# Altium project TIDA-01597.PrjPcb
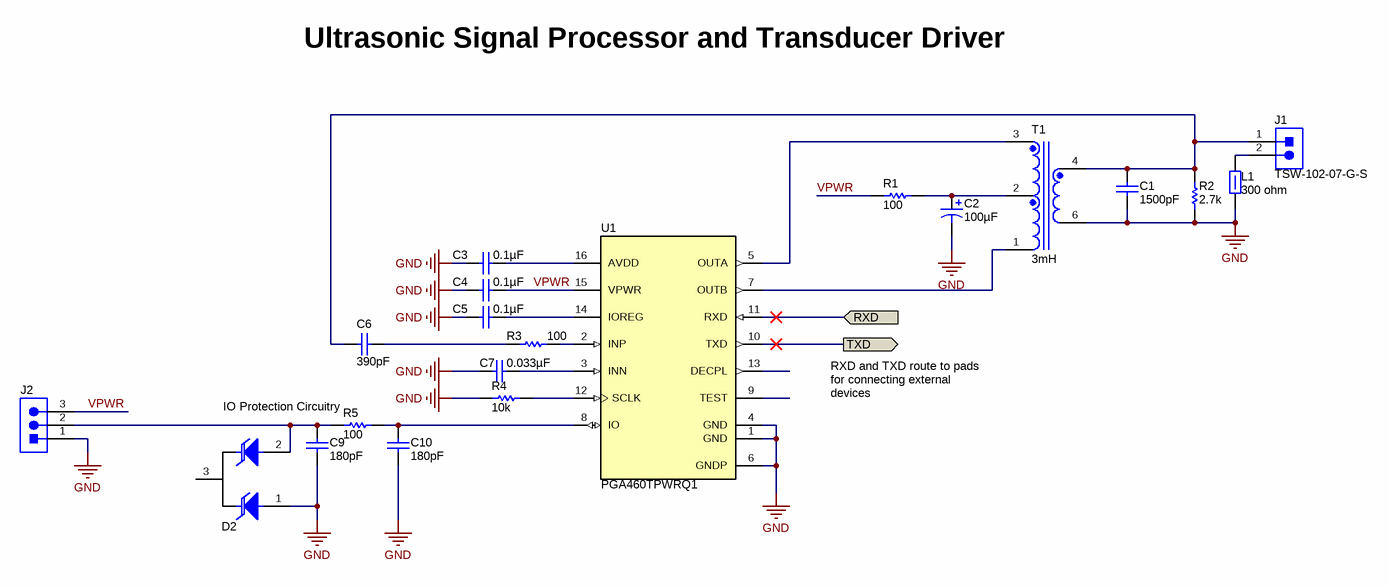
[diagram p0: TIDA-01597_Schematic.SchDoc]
CopyrightYear: 2017; EVM_Orderable: N/A; PCB_Layout: Luis Cordova; PCB_Rev: E1; PRJ_Customer: N/A; PRJ_Engineer: Luis Cordova; PRJ_Number: TIDA-01597; PRJ_Title: Ultrasonic Object Detection for Park Assist; SCH_Rev: E1; TechSupport: http://www.ti.com/support; TID: TIDA-01597
4 sheets, 43 parts. Net scope: flat (ports and power ports of the same name join across sheets).
Board file: TIDA-01597_PCB.PcbDoc
Sheets:
  TIDA-01597_Schematic.SchDoc
  TIDA-01597_CoverSheet.SchDoc
  TIDA-01597_EVMHardware.SchDoc
  TCI-level-translator.SchDoc

## Sheet TIDA-01597_Schematic.SchDoc
size 431 x 279 mm; Date: Not shown in title block; ApprovedBy: Not shown in title block; CheckedBy: Not shown in title block; Author: Not shown in title block; CompanyName: Not shown in title block; Engineer: Not shown in title block; Organization: Not shown in title block; Address1: Not shown in title block; Address2: Not shown in title block; Address3: Not shown in title block; Address4: Not shown in title block; DocumentNumber: 1; Revision: Use project parameter SCH_Rev; SheetNumber: 2; SheetTotal: 3; PageSetup: Record=PageOptions¦CenterHorizontal=True¦CenterVertical=True¦PrintScale=0.64¦XCorrection=1.00¦YCorrection=1.00¦PrintKind=0¦BorderSize=5000000¦LeftOffset=0¦BottomOffset=0¦Orientation=2¦PaperLength=1000¦PaperWidth=1000¦Scale=100¦PaperSource=15¦PrintQuality=600¦MediaType=1¦DitherType=10¦PrintScaleMode=1¦PaperKind=Letter

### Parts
C1  ValueDisplayed: 1500pF  [0603]  (hidden comment: GRM188R72A152KA01D)
C2  ValueDisplayed: 100µF  [SM_RADIAL_F]  (hidden comment: EEE-FK1V101P)
C3  ValueDisplayed: 0.1µF  [0603M]  (hidden comment: C1608X7R1E104K080AA)
C4  ValueDisplayed: 0.1µF  [0603L]  (hidden comment: C1608X7R1E104K080AA)
C5  ValueDisplayed: 0.1µF  [0603L]  (hidden comment: C1608X7R1E104K080AA)
C6  ValueDisplayed: 390pF  [0603]  (hidden comment: GRM1885C2A391JA01D)
C7  ValueDisplayed: 0.033µF  [0603]  (hidden comment: 06035C333JAT2A)
C9  ValueDisplayed: 180pF  [0603]  (hidden comment: GRM1885C1H181JA01D)
C10  ValueDisplayed: 180pF  [0603]  (hidden comment: GRM1885C1H181JA01D)
D2  MMBZ27VCL-7-F  [SOT-23]  (value not drawn)
J1  TSW-102-07-G-S  [TSW-102-07-G-S]
J2  TSW-103-07-G-S  [TSW-103-07-G-S]  (value not drawn)
L1  ValueDisplayed: 300 ohm  [0603]  (hidden comment: 74279264)
R1  ValueDisplayed: 100  [0603]  (hidden comment: CRCW0603100RJNEA)
R2  ValueDisplayed: 2.7k  [0603]  (hidden comment: RC0603JR-072K7L)
R3  ValueDisplayed: 100  [0603]  (hidden comment: CRCW0603100RJNEA)
R4  ValueDisplayed: 10k  [0603L]  (hidden comment: RC0603JR-0710KL)
R5  ValueDisplayed: 100  [0603]  (hidden comment: CRCW0603100RFKEA)
T1  ValueDisplayed: 3mH  [TDK_B78416A2232A003]  (hidden comment: B78416A2232A003)
U1  PGA460TPWRQ1  [PW0016A_N]

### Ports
RXD (in), TXD (out)

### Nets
GND: C1.2 C2.2(-) C3.2 C4.2 C5.2 C7.2 C9.2 C10.2 D2.1 J2.1 L1.1 R2.1 R4.1 T1.6 U1.1(GND) U1.4(GND) U1.6(GNDP)
RXD: U1.11(RXD) ; port RXD
TXD: U1.10(TXD) ; port TXD
VPWR: C4.1 J2.3 R1.2 U1.15(VPWR)
NetC1_1: C1.1 C6.2 J1.1 R2.2 T1.4
NetC2_1: C2.1(+) R1.1 T1.2
NetC3_1: C3.1 U1.16(AVDD)
NetC5_1: C5.1 U1.14(IOREG)
NetC6_1: C6.1 R3.1
NetC7_1: C7.1 U1.3(INN)
NetC9_1: C9.1 D2.2 J2.2 R5.1
NetC10_1: C10.1 R5.2 U1.8(IO)
NetJ1_2: J1.2 L1.2
NetR3_2: R3.2 U1.2(INP)
NetR4_2: R4.2 U1.12(SCLK)
NetT1_1: T1.1 U1.7(OUTB)
NetT1_3: T1.3 U1.5(OUTA)

Not connected (* = marked no-connect by the designer): D2 3; U1 9(TEST) 13(DECPL)

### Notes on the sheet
- Ultrasonic Signal Processor and Transducer Driver
- (near R5) IO Protection Circuitry
- RXD and TXD route to pads for connecting external devices

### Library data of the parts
C1 = GRM188R72A152KA01D: CAP, CERM, 1500 pF, 100 V, +/- 10%, X7R, 0603; Manufacturer: MuRata; Polarized: N; CompType: Capacitor; Value: 1500pF; U/M: EA; Cap_F: 0.0000000015; Tolerance_%: 10; Value1: Unknown; VDC_V: 100; Value2: 100V; TaMin_C: -55; TaMax_C: 125; SizeArea_mm2: 1.28; SizeAreaWB_mm2: 4.68; SizeX_mm: 1.6; SizeY_mm: 0.8; SizeZ_mm: 1; AEC Category: Q200
C2 = EEE-FK1V101P: CAP, AL, 100 µF, 35 V, +/- 20%, 0.16 ohm, AEC-Q200 Grade 2, SMD; Manufacturer: Panasonic; Polarized: Y; CompType: Capacitor; Value: 100uF; U/M: EA; Cap_F: 0.0001; Tolerance_%: 20; VDC_V: 35; Value2: 35V; ESR_ohm: 0.16; IRMS_A: 0.6; TaMin_C: -55; TaMax_C: 105; Cap_Case: F; SizeAreaWB_mm2: 123.6; SizeArea_mm2: 83; SizeX_mm: 10; SizeY_mm: 8.3; SizeZ_mm: 10.2; AEC Category: Q200; AEC Grade: 2
C3-C5 = C1608X7R1E104K080AA: CAP, CERM, 0.1 µF, 25 V, +/- 10%, X7R, 0603; Manufacturer: TDK; Polarized: N; CompType: Capacitor; Value: 0.1uF; U/M: EA; Cap_F: 0.0000001; Tolerance_%: 10; Value1: Unknown; VDC_V: 25; Value2: 25V; TaMin_C: -55; TaMax_C: 125; Cap_Case: 0603; SizeArea_mm2: 1.28; SizeAreaWB_mm2: 4.68; SizeX_mm: 1.6; SizeY_mm: 0.8; SizeZ_mm: 1; AEC Category: Q200
C6 = GRM1885C2A391JA01D: CAP, CERM, 390 pF, 100 V, +/- 5%, C0G/NP0, 0603; Manufacturer: MuRata; Polarized: N; CompType: Capacitor; Value: 390pF; U/M: EA; Cap_F: 0.00000000039; Tolerance_%: 5; Value1: Unknown; VDC_V: 100; Value2: 100V; TaMin_C: -55; TaMax_C: 125; SizeArea_mm2: 1.28; SizeAreaWB_mm2: 4.68; SizeX_mm: 1.6; SizeY_mm: 0.8; SizeZ_mm: 1; AEC Category: Q200
C7 = 06035C333JAT2A: CAP, CERM, 0.033 µF, 50 V, +/- 5%, X7R, 0603; Manufacturer: AVX; Polarized: N; CompType: Capacitor; Value: 0.033uF; U/M: EA; Cap_F: 0.000000033; Tolerance_%: 5; Value1: Unknown; VDC_V: 50; Value2: 50V; TaMin_C: -55; TaMax_C: 125; SizeArea_mm2: 1.28; SizeAreaWB_mm2: 4.68; SizeX_mm: 1.6; SizeY_mm: 0.8; SizeZ_mm: 1; AEC Category: Q200
C9 C10 = GRM1885C1H181JA01D: CAP, CERM, 180 pF, 50 V,+/- 5%, C0G/NP0, 0603; Manufacturer: MuRata; Polarized: N; CompType: Capacitor; Value: 180pF; U/M: EA; Cap_F: 0.00000000018; Tolerance_%: 5; VDC_V: 50; Value2: 50V; TaMin_C: -55; TaMax_C: 125; SizeArea_mm2: 1.28; SizeAreaWB_mm2: 4.68; SizeX_mm: 1.6; SizeY_mm: 0.8; SizeZ_mm: 1; AEC Category: Q200; Green_Lifecycle: Active; Green_REACh: Passed
D2 = MMBZ27VCL-7-F: Diode, TVS, Uni, 27 V, 38 Vc, SOT-23; Manufacturer: Diodes Inc.; SymbolCreator: a0411947; Value: 27V; U/M: EA; Power_W: 0.225; Vr_V: 27; Value1: 0.225W; RJA_CperW: 556; SizeAreaWB_mm2: 14; SizeArea_mm2: 7.5; SizeX_mm: 2.5; SizeY_mm: 3; SizeZ_mm: 1.1; AEC Category: Q101; AEC Qualified: N
J1 = TSW-102-07-G-S: Header, 100mil, 2x1, Gold, TH; Manufacturer: Samtec; SymbolCreator: a0412235; Pitch_mm: 2.54; Gender: Male; Shrouded: N; Row_Count: 1; Current_A: 6.3; Voltage_V: 550; Cert_CSA: Y
J2 = TSW-103-07-G-S: Header, 100mil, 3x1, Gold, TH; Manufacturer: Samtec; SymbolCreator: a0799628; Pitch_mm: 2.54; Gender: Male; Shrouded: N; Row_Count: 1; Current_A: 6.3; Voltage_V: 550; Cert_CSA: Y
L1 = 74279264: Ferrite Bead, 300 ohm @ 100 MHz, 0.2 A, 0603; Manufacturer: Wurth Elektronik; Value: 300 ohm; Imax_A: 0.2; DCR_ohm: 0.35; Value1: 0.35 ohm; Value2: 0.2A; SizeAreaWB_mm2: 4.68; SizeArea_mm2: 1.28; SizeX_mm: 1.6; SizeY_mm: 0.8; SizeZ_mm: 1; ZTyp@100MHz_Ohm: 300; Ztyp@1GHz_Ohm: 279.491
R1 = CRCW0603100RJNEA: RES, 100, 5%, 0.1 W, 0603; Manufacturer: Vishay-Dale; CompType: Resistor; Value: 100; Value_Code: 100R; Tolerance_%: 5; Power_W: 0.1; Value2: 0.1W; VDC_V: 75; TempCo: 200 ppm/C; SizeArea_mm2: 1.28; SizeX_mm: 1.6; SizeY_mm: 0.8; SizeZ_mm: 1; EIA_Code: E24; U/M: EA; AEC Category: Q200; Green_Lifecycle: Active; Green_REACh: Passed
R2 = RC0603JR-072K7L: RES, 2.7 k, 5%, 0.1 W, 0603; Manufacturer: Yageo America; CompType: Resistor; Value: 2.7k; Res_ohm: 2700; Value_Code: 2k70; Tolerance_%: 5; Power_W: 0.1; Value2: 0.1W; VDC_V: 50; TempCo: 100 ppm/C; SizeArea_mm2: 1.28; SizeX_mm: 1.6; SizeY_mm: 0.8; SizeZ_mm: 1; EIA_Code: E24; U/M: EA; AEC Category: Q200
R3 = CRCW0603100RJNEA: RES, 100, 5%, 0.1 W, 0603; Manufacturer: Vishay-Dale; CompType: Resistor; Value: 100; Value_Code: 100R; Tolerance_%: 5; Power_W: 0.1; Value2: 0.1W; VDC_V: 75; TempCo: 200 ppm/C; SizeArea_mm2: 1.28; SizeX_mm: 1.6; SizeY_mm: 0.8; SizeZ_mm: 1; EIA_Code: E24; U/M: EA; AEC Category: Q200
R4 = RC0603JR-0710KL: RES, 10 k, 5%, 0.1 W, 0603; Manufacturer: Yageo America; CompType: Resistor; Value: 10k; Res_ohm: 10000; Value_Code: 10k0; Tolerance_%: 5; Power_W: 0.1; Value2: 0.1W; VDC_V: 50; TempCo: 100 ppm/C; SizeArea_mm2: 1.28; SizeX_mm: 1.6; SizeY_mm: 0.8; SizeZ_mm: 1; EIA_Code: E24; U/M: EA; AEC Category: Q200
R5 = CRCW0603100RFKEA: RES, 100, 1%, 0.1 W, 0603; Manufacturer: Vishay-Dale; CompType: Resistor; Value: 100; Value_Code: 100R; Tolerance_%: 1; Power_W: 0.1; Value2: 0.1W; VDC_V: 75; TempCo: 100 ppm/C; SizeArea_mm2: 1.28; SizeX_mm: 1.6; SizeY_mm: 0.8; EIA_Code: E96; U/M: EA; AEC Category: Q200; Green_Lifecycle: Active; Green_REACh: Passed
T1 = B78416A2232A003: Transformer, 3 mH, SMT; Manufacturer: TDK; SymbolCreator: Altium; Value: 3mH; Lp: 3000; Ns1toNp: 0.1188
U1 = PGA460TPWRQ1: PGA460TPWRQ1, PW0016A (TSSOP-16); Manufacturer: Texas Instruments; SymbolCreator: Altium; SizeArea_mm2: 32; SizeAreaWB_mm2: 58.8; SizeX_mm: 6.4; SizeY_mm: 5; SizeZ_mm: 1.2; CompType: IC; U/M: EA

## Sheet TIDA-01597_CoverSheet.SchDoc
size 431 x 279 mm; Date: Not shown in title block; ApprovedBy: Not shown in title block; CheckedBy: Not shown in title block; Author: Not shown in title block; CompanyName: Not shown in title block; Engineer: Not shown in title block; Organization: Not shown in title block; Address1: Not shown in title block; Address2: Not shown in title block; Address3: Not shown in title block; Address4: Not shown in title block; DocumentNumber: 1; Revision: Use project parameter SCH_Rev; SheetNumber: 1; SheetTotal: 3; PageSetup: Record=PageOptions¦CenterHorizontal=True¦CenterVertical=True¦PrintScale=1.00¦XCorrection=1.00¦YCorrection=1.00¦PrintKind=0¦BorderSize=5000000¦LeftOffset=0¦BottomOffset=0¦Orientation=2¦PaperLength=1000¦PaperWidth=1000¦Scale=100¦PaperSource=15¦PrintQuality=600¦MediaType=1¦DitherType=10¦PaperKind=Letter¦PrintScaleMode=1
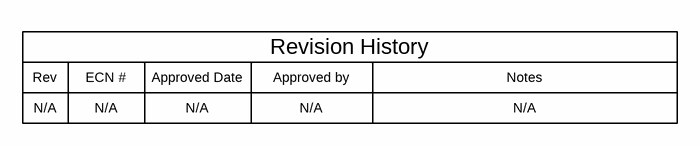
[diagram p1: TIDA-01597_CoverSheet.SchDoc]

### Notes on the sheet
- Rev
- N/A
- ECN #
- Approved Date
- Approved by
- Revision History
- Notes

## Sheet TIDA-01597_EVMHardware.SchDoc
size 431 x 279 mm; Date: Not shown in title block; ApprovedBy: Not shown in title block; CheckedBy: Not shown in title block; Author: Not shown in title block; CompanyName: Not shown in title block; Engineer: Not shown in title block; Organization: Not shown in title block; Address1: Not shown in title block; Address2: Not shown in title block; Address3: Not shown in title block; Address4: Not shown in title block; DocumentNumber: 1; Revision: Use project parameter SCH_Rev; SheetNumber: 3; SheetTotal: 3; PageSetup: Record=PageOptions¦CenterHorizontal=True¦CenterVertical=True¦PrintScale=1.00¦XCorrection=1.00¦YCorrection=1.00¦PrintKind=0¦BorderSize=5000000¦LeftOffset=0¦BottomOffset=0¦Orientation=2¦PaperLength=1000¦PaperWidth=1000¦Scale=100¦PaperSource=15¦PrintQuality=600¦MediaType=1¦DitherType=10¦PaperKind=Letter¦PrintScaleMode=1
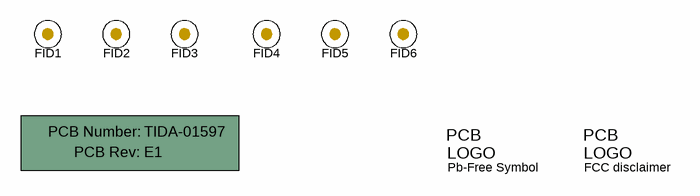
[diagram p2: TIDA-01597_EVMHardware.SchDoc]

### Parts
!PCB1  TIDA-01597  (value not drawn)  (mechanical)
FID1  Fiducial  [Fiducial10-20]  (value not drawn)
FID2  Fiducial  [Fiducial10-20]  (value not drawn)
FID3  Fiducial  [Fiducial10-20]  (value not drawn)
FID4  Fiducial  [Fiducial10-20]  (value not drawn)
FID5  Fiducial  [Fiducial10-20]  (value not drawn)
FID6  Fiducial  [Fiducial10-20]  (value not drawn)
Logo2  Pb-Free Symbol  [Pb-Free_Overlay_Small]  (no BOM)
Logo3  FCC disclaimer  [FCC_disclaimer]  (no BOM)

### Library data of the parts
!PCB1 = PCB: Printed Circuit Board; Manufacturer: Any; SymbolCreator: a0412235
FID1-FID6 = Fiducial: Fiducial mark.  There is nothing to buy or mount.; SymbolCreator: codlsc
Logo2 = Pb-Free: SymbolCreator: a0412235
Logo3 = FCC_disclaimer: SymbolCreator: codlsc

## Sheet TCI-level-translator.SchDoc
size 431 x 279 mm; Date: Not shown in title block; ApprovedBy: Not shown in title block; CheckedBy: Not shown in title block; Author: Not shown in title block; CompanyName: Not shown in title block; Engineer: Not shown in title block; Organization: Not shown in title block; Address1: Not shown in title block; Address2: Not shown in title block; Address3: Not shown in title block; Address4: Not shown in title block; DocumentNumber: 1; Revision: Use project parameter SCH_Rev; SheetNumber: 2; SheetTotal: 3; PageSetup: Record=PageOptions¦CenterHorizontal=True¦CenterVertical=True¦PrintScale=1.00¦XCorrection=1.00¦YCorrection=1.00¦PrintKind=0¦BorderSize=5000000¦LeftOffset=0¦BottomOffset=0¦Orientation=2¦PaperLength=1000¦PaperWidth=1000¦Scale=100¦PaperSource=15¦PrintQuality=600¦MediaType=1¦DitherType=10¦PaperKind=Letter¦PrintScaleMode=1
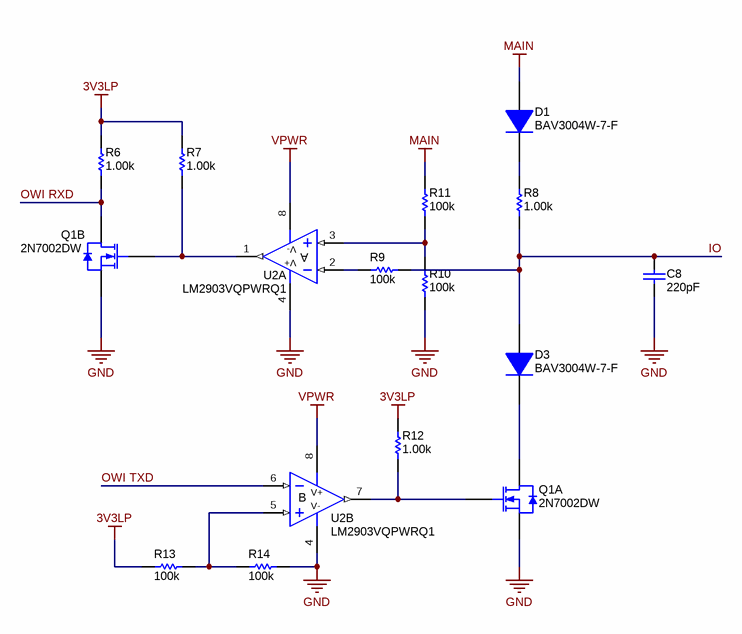
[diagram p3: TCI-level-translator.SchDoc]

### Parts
C8  ValueDisplayed: 220pF  [0603]  (hidden comment: 06031C221KAT2A)
D1  BAV3004W-7-F  [SOD-123]
D3  BAV3004W-7-F  [SOD-123]
Q1  2N7002DW  [SOT-363]  (parts A,B of 2)
R6  ValueDisplayed: 1.00k  [0603]  (hidden comment: CRCW06031K00FKEA)
R7  ValueDisplayed: 1.00k  [0603]  (hidden comment: CRCW06031K00FKEA)
R8  ValueDisplayed: 1.00k  [0603]  (hidden comment: CRCW06031K00FKEA)
R9  ValueDisplayed: 100k  [0603]  (hidden comment: CRCW0603100KFKEA)
R10  ValueDisplayed: 100k  [0603]  (hidden comment: CRCW0603100KFKEA)
R11  ValueDisplayed: 100k  [0603]  (hidden comment: CRCW0603100KFKEA)
R12  ValueDisplayed: 1.00k  [0603]  (hidden comment: CRCW06031K00FKEA)
R13  ValueDisplayed: 100k  [0603]  (hidden comment: CRCW0603100KFKEA)
R14  ValueDisplayed: 100k  [0603]  (hidden comment: CRCW0603100KFKEA)
U2  LM2903VQPWRQ1  [PW0008A_N]  (parts A,B of 2)

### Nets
3V3LP: R6.2 R7.2 R12.2 R13.2
GND: C8.2 Q1.1(S) Q1.4(S) R10.2 R14.1 U2.4(V-)
MAIN: D1.2(A) R11.1
VPWR: U2.8(V+)
IO: C8.1 D3.2(A) R8.1 R9.1
OWI RXD: Q1.3(D) R6.1
OWI TXD: U2.6(IN-)
NetD1_1: D1.1(K) R8.2
NetD3_1: D3.1(K) Q1.6(D)
NetQ1_2: Q1.2(G) R12.1 U2.7(OUT)
NetQ1_5: Q1.5(G) R7.1 U2.1(OUT)
NetR9_2: R9.2 U2.2(IN-)
NetR10_1: R10.1 R11.2 U2.3(IN+)
NetR13_1: R13.1 R14.2 U2.5(IN+)

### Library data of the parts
C8 = 06031C221KAT2A: CAP, CERM, 220 pF, 100 V,+/- 10%, X7R, 0603; Manufacturer: AVX; Polarized: N; CompType: Capacitor; Value: 220pF; U/M: EA; Cap_F: 0.00000000022; Tolerance_%: 10; ESR_ohm: 0.579; Value1: 0.579 ohm; VDC_V: 100; Value2: 100V; TaMin_C: -55; TaMax_C: 125; SizeArea_mm2: 1.28; SizeAreaWB_mm2: 4.68; SizeX_mm: 1.6; SizeY_mm: 0.8; SizeZ_mm: 1; AEC Category: Q200; Green_Lifecycle: Active; Green_REACh: Passed
D1 D3 = BAV3004W-7-F: Diode, Switching, 350 V, 0.225 A, SOD-123; Manufacturer: Diodes Inc.; U/M: EA; Vf_V: 1.25; Value: 350V; Value1: 0.225A; Value2: 1.25V; Io_A: 0.225; Vr_V: 350; TJmax_C: 150; SizeAreaWB_mm2: 13.095; SizeArea_mm2: 6.545; SizeX_mm: 3.85; SizeY_mm: 1.7; SizeZ_mm: 1.35; AEC Category: Q101; Green_Lifecycle: Not Set; Green_REACh: Incomplete
Q1 = 2N7002DW: MOSFET, 2-CH, N-CH, 60 V, 0.115 A, SOT-363; Manufacturer: Fairchild Semiconductor; Alternate Manufacturer: None; U/M: EA; ChType: N; Value: 60V; VdsMax_V: 60; Value1: ? ohm; Value2: ? nC; Vgs_V: 20; IdsMax_A: 0.115; SizeAreaWB_mm2: 10.24; SizeArea_mm2: 4.84; SizeX_mm: 2.2; SizeZ_mm: 1.1; AEC Category: Q101; Green_Lifecycle: Active; Green_REACh: Passed
R6-R8 R12 = CRCW06031K00FKEA: RES, 1.00 k, 1%, 0.1 W, 0603; Manufacturer: Vishay-Dale; CompType: Resistor; Value: 1.00k; Res_ohm: 1000; Value_Code: 1k00; Tolerance_%: 1; Power_W: 0.1; Value2: 0.1W; VDC_V: 75; TempCo: 100 ppm/C; SizeArea_mm2: 1.28; SizeX_mm: 1.6; SizeY_mm: 0.8; EIA_Code: E96; U/M: EA; AEC Category: Q200; Green_Lifecycle: Active; Green_REACh: Passed
R9-R11 R13 R14 = CRCW0603100KFKEA: RES, 100 k, 1%, 0.1 W, 0603; Manufacturer: Vishay-Dale; CompType: Resistor; Value: 100k; Res_ohm: 100000; Tolerance_%: 1; Power_W: 0.1; Value2: 0.1W; VDC_V: 75; TempCo: 100 ppm/C; SizeArea_mm2: 1.28; SizeX_mm: 1.6; SizeY_mm: 0.8; EIA_Code: E96; U/M: EA; AEC Category: Q200; Green_Lifecycle: Active; Green_REACh: Passed
U2 = LM2903VQPWRQ1: Automotive Catalog Dual Differential Comparator, PW0008A (TSSOP-8); Manufacturer: Texas Instruments; SymbolCreator: a0799628; SizeArea_mm2: 19.2; SizeAreaWB_mm2: 42; SizeX_mm: 6.4; SizeY_mm: 3; SizeZ_mm: 1.2; CompType: IC; U/M: EA

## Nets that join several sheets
GND: TIDA-01597_Schematic (17 pins), TCI-level-translator (6 pins)

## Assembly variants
001: not fitted FID1 FID2 FID3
